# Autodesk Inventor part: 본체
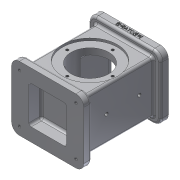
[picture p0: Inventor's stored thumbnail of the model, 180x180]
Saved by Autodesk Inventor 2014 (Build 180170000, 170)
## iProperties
Created: 2017-08
Part Number: 본체
Material: 알루미늄 6061
Document SubType Name: Modeling
Designer: user
Mass: 871.829 g
Surface Area: 643.154 cm^2
Volume: 321.708 cm^3
Density: 2.71 g/cm^3
Appearance: 알루미늄 - 평지
Author: user
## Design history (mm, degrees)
sketch "스케치1"
  geometry: L1 (-46, 41)-(46, 41); L2 (46, 41)-(46, -41); L3 (46, -41)-(-46, -41); L4 (-46, -41)-(-46, 41); L5 (-46, 41)-(46, -41); L6 (46, 41)-(-46, -41); 1 further point
  constraints: 12 end point, 2 midpoint, 2 parallel, 1 horizontal, 1 perpendicular
  dimensions: "d0" = 92 distance between parallel lines of L4 L2; "d1" = 82 distance between parallel lines of L1 L3
extrude "돌출1" new body sketch "스케치1" distance "d2" = 10; taper "d3" = 0 deg
sketch "스케치2"
  geometry: L1 (-37, -33)-(37, -33); L2 (37, -33)-(37, 33); L3 (37, 33)-(-37, 33); L4 (-37, 33)-(-37, -33); L5 (-37, -33)-(37, 33); L6 (37, -33)-(-37, 33); 1 further point
  constraints: 12 end point, 2 midpoint, 2 parallel, 1 horizontal, 1 perpendicular
  dimensions: "d4" = 74 distance between parallel lines of L2 L4; "d5" = 66 distance between parallel lines of L1 L3
extrude "돌출2" join sketch "스케치2" distance "d6" = 88; taper "d7" = 0 deg
sketch "스케치3"
  geometry: L1 (-46, -41)-(46, -41); L2 (46, -41)-(46, 41); L3 (46, 41)-(-46, 41); L4 (-46, 41)-(-46, -41); L5 (-46, -41)-(46, 41); L6 (46, -41)-(-46, 41); 1 further point
  constraints: 12 end point, 2 midpoint, 2 parallel, 1 horizontal, 1 perpendicular
  dimensions: "d9" = 82 distance between parallel lines of L1 L3; "d10" = 92 distance between parallel lines of L4 L2
extrude "돌출3" join sketch "스케치3" distance "d11" = 10; taper "d12" = 0 deg
sketch "스케치5"
  geometry: L1 (0, 10)-(92, 10) reference; L2 (92, -98)-(0, -98) reference; 3 further points
  constraints: 1 midpoint, 1 vertical alignment, 1 other
  dimensions: "d13" = 4 distance from line of point (46, 6) L1
feature "엠보싱1" sketch "스케치5" dims "d0" = 92, "d1" = 82, "d14" = 0.5, "d15" = 0
sketch "스케치6"
  geometry: L1 (-24, -24)-(24, -24); L2 (24, -24)-(24, 24); L3 (24, 24)-(-24, 24); L4 (-24, 24)-(-24, -24); L5 (-24, -24)-(24, 24); L6 (24, -24)-(-24, 24); 1 further point
  constraints: 12 end point, 2 midpoint, 2 parallel, 1 horizontal, 1 perpendicular
  dimensions: "d16" = 48 distance between parallel lines of L1 L3; "d17" = 48 distance between parallel lines of L2 L4
extrude "돌출4" cut sketch "스케치6" distance "d18" = 16; taper "d19" = 0 deg
sketch "스케치8"
  geometry: L1 (54, 56.352)-(54, -41.722); L2 (0, 41)-(0, -41) reference; L3 (10, 33)-(98, 33) reference; L4 (54, 33)-(89, 33); L5 (89, 33)-(89, 30); L6 (89, 30)-(78, 30); L7 (78, 30)-(78, -30); L8 (78, -30)-(89, -30); L9 (10, -33)-(98, -33) reference; L10 (89, -30)-(89, -33); L11 (54, -33)-(89, -33); 1 further point
  constraints: 16 end point, 4 point on line, 3 perpendicular, 2 midpoint, 2 parallel, 1 collinear, 1 vertical
  dimensions: "d21" = 54 distance between parallel lines of L2 L1; "d22" = 48 diameter of L7 L1; "d23" = 70 diameter of L5 L1; "d24" = 70 diameter of L10 L1; "d25" = 3 distance between parallel lines of L3 L6; "d26" = 3 distance between parallel lines of L11 L8
revolve "회전1" sketch "스케치8" stored, may be unused: angle "d27" = 90 deg
sketch "스케치9"
  geometry: L1 (-26, -26)-(26, -26); L2 (26, -26)-(26, 26); L3 (26, 26)-(-26, 26); L4 (-26, 26)-(-26, -26); L5 (-26, -26)-(26, 26); L6 (26, -26)-(-26, 26); 1 further point
  constraints: 12 end point, 2 midpoint, 2 parallel, 1 horizontal, 1 perpendicular
  dimensions: "d28" = 52 distance between parallel lines of L2 L4; "d29" = 52 distance between parallel lines of L1 L3
extrude "돌출5" cut sketch "스케치9" distance "d30" = 8; taper "d31" = 0 deg
sketch "스케치10"
  geometry: L1 (-22, -22)-(22, -22); L2 (22, -22)-(22, 22); L3 (22, 22)-(-22, 22); L4 (-22, 22)-(-22, -22); L5 (-22, -22)-(22, 22); L6 (22, -22)-(-22, 22); 1 further point
  constraints: 12 end point, 2 midpoint, 2 parallel, 1 horizontal, 1 perpendicular
  dimensions: "d32" = 44 distance between parallel lines of L2 L4; "d33" = 44 distance between parallel lines of L1 L3
extrude "돌출6" cut sketch "스케치10" distance "d34" = 74; taper "d35" = 0 deg
fillet "모깎기1" dims "d36" = 10
sketch "스케치11" dims "d37" = 58
  geometry: C1 r 35 at (0, 0) reference; C2 r 24 at (0, 0) reference; 3 further points
  constraints: 2 vertical alignment, 1 coincident, 2 other
hole "구멍1" sketch "스케치11" at (0, 29) diameter "d38" = 3.459; stored, may be unused: countersink angle "d42" = 90 deg, drill point angle "d44" = 118 deg; dims "d39" = 4, "d40" = 4, "d41" = 2, "d43" = 6
sketch "스케치12"
  geometry: L1 (-36, -31)-(36, -31); L2 (36, -31)-(36, 31); L3 (36, 31)-(-36, 31); L4 (-36, 31)-(-36, -31); L5 (-36, -31)-(36, 31); L6 (36, -31)-(-36, 31); A1 r 10 centre (36, 31) between (46, 31) and (36, 41) reference; A2 r 10 centre (36, -31) between (36, -41) and (46, -31) reference; 1 further point
  constraints: 12 end point, 2 midpoint, 2 parallel, 1 horizontal, 1 perpendicular
  dimensions: "d48" = 62 distance between parallel lines of L1 L3; "d49" = 72 distance between parallel lines of L4 L2
hole "구멍2" sketch "스케치12" at (-36, 31), (-36, -31), (36, -31), (36, 31) diameter "d50" = 3.459; stored, may be unused: countersink angle "d54" = 90 deg, drill point angle "d56" = 118 deg; dims "d51" = 4, "d52" = 4, "d53" = 2, "d55" = 6
node "작업 평면1"
sketch "스케치13"
  geometry: L1 (66, 0)-(0, 0) reference; L2 (0, 88)-(66, 88) reference; L3 (33, 88)-(33, 0); L4 (64, -10)-(2, -10) reference; 3 further points
  constraints: 2 end point, 2 midpoint, 2 point on line
  dimensions: "d57" = 38 distance from line of L4 point (33, 28); "d58" = 42 distance of point (33, 70) point (33, 28)
hole "구멍3" sketch "스케치13" at (33, 70), (33, 28) diameter "d59" = 4.459; stored, may be unused: countersink angle "d63" = 90 deg, drill point angle "d65" = 118 deg; dims "d60" = 20, "d61" = 4, "d62" = 2, "d64" = 6
fillet "모깎기2" dims "d66" = 3
chamfer "모따기1" distance "d67" = 1; stored, may be unused: second distance "d68" = 2, angle "d69" = 45 deg
fillet "모깎기3" dims "d70" = 3
fillet "모깎기4" dims "d71" = 3
node "솔리드1"
pattern_circular "원형 패턴1" dims angle "d46" = 360 deg
mirror "대칭1"
mirror "대칭2"
